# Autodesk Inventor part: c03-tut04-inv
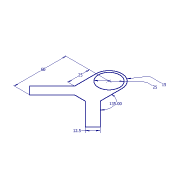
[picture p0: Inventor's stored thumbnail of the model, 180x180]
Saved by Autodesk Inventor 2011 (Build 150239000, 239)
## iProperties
Created: 2010-01
Part Number: c03-tut04-inv
Document SubType Name: Modeling
Designer: CADSoft
Density: 1 g/cm^3
Author: CADSoft
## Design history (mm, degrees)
sketch "Sketch1"
  geometry: L1 (-41.161, -51.161)-(-32.322, -60); L2 (-32.322, -60)-(-6.25, -33.928); L3 (-6.25, -33.928)-(6.25, -33.928); L4 (6.25, -33.928)-(32.322, -60); L5 (32.322, -60)-(41.161, -51.161); L6 (41.161, -51.161)-(15, -25); L7 (15, -25)-(15, 0); L8 (-15, 0)-(-15, -25); L9 (-15, -25)-(-41.161, -51.161); C1 r 12.5 at (0, 0); A1 r 15 centre (0, 0) between (15, 0) and (-15, 0); 2 further points
  constraints: 18 end point, 5 equal length, 3 coincident, 3 parallel, 2 centre point, 2 perpendicular, 2 point on circle, 2 tangent, 1 horizontal, 1 vertical, 1 other
  dimensions: "d0" = 25 distance of L8.start L8.end; "d1" = 60 vertical distance of L1.end A1.centre; "d2" = 12.5 distance of L4.end L5.end; "d3" = 135 deg angle of L6 L7; "d4" = 15 radius of A1; "d5" = 25 diameter of C1
